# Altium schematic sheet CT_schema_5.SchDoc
size 369 x 245 mm
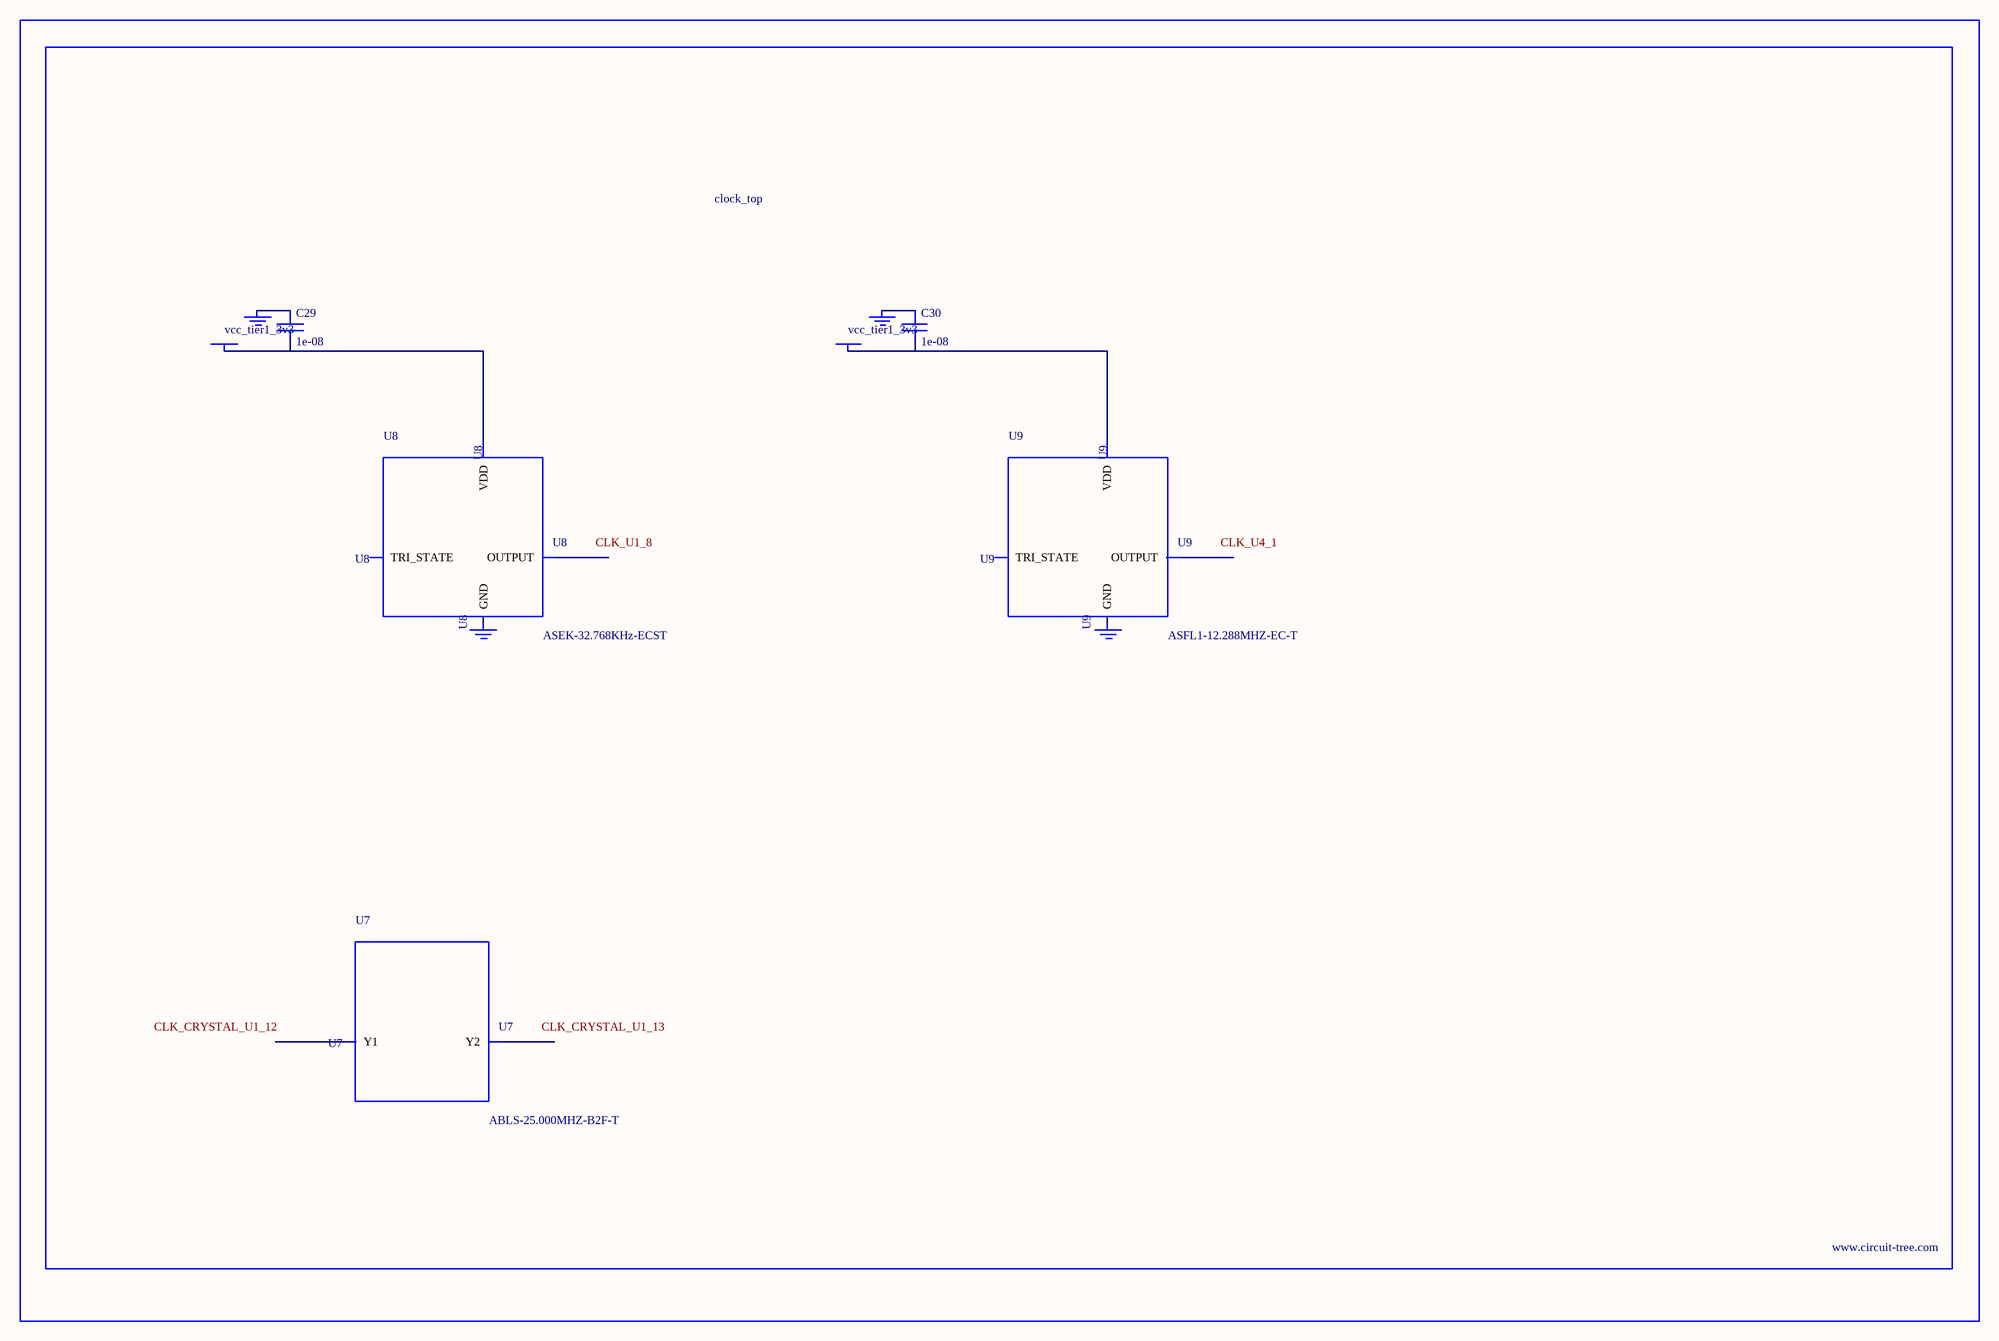
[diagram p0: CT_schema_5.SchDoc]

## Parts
BORDER4  (no value)
C29  1e-08  [C0402]
C30  1e-08  [C0402]
GND_INSTANCE_4_0  (no value)
GND_INSTANCE_4_1  (no value)
GND_INSTANCE_4_2  (no value)
GND_INSTANCE_4_3  (no value)
POWER_INSTANCE_4_0  vcc_tier1_3v3
POWER_INSTANCE_4_1  vcc_tier1_3v3
U7  ABLS-25.000MHZ-B2F-T  [ABLS-25.000MHZ-B2F-T]
U8  ASEK-32.768KHz-ECST  [ASEK]
U9  ASFL1-12.288MHZ-EC-T  [ASFL1]

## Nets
NetC29_1: C29.1 GND_INSTANCE_4_0.0(GND)
NetC29_2: C29.2 POWER_INSTANCE_4_0.0(PWR) U8.4(VDD)
NetC30_1: C30.1 GND_INSTANCE_4_2.0(GND)
NetC30_2: C30.2 POWER_INSTANCE_4_1.0(PWR) U9.4(VDD)

Not connected (* = marked no-connect by the designer): GND_INSTANCE_4_1 0(GND); GND_INSTANCE_4_3 0(GND); U7 1(Y1) 2(Y2); U8 1(TRI_STATE) 2(GND) 3(OUTPUT); U9 1(TRI_STATE) 2(GND) 3(OUTPUT)

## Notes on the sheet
- Labels drawn without touching a wire or pin: CLK_CRYSTAL_U1_12, CLK_CRYSTAL_U1_13, CLK_U1_8, CLK_U4_1

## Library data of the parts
BORDER4 = BORDER_PAGE4
C29 C30 = C0402C103K3RAC
GND_INSTANCE_4_0-GND_INSTANCE_4_3 = GND
POWER_INSTANCE_4_0 POWER_INSTANCE_4_1 = PWR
